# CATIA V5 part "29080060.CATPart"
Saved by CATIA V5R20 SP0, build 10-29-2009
Part number: 29080060
Definition: NONE
Nomenclature: 29080060
Source: Unknown
Description: 29080060
Bounding box of the stored display mesh (mm): x -30 to 44.548, y -54 to 88.548, z -44 to 44
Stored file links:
  C:\Users\Utente\Desktop\IO LAVORO\3D X SITO CF\X SITO\PLASTICA\RF1\29080060.CATPart
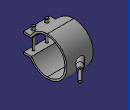
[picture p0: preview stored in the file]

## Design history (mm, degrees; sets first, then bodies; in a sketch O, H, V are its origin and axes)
Body1 "29080060" (main body)
  Solid1: solid without history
